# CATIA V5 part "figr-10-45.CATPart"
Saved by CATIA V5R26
Part number: Part1
Bounding box of the stored display mesh (mm): x -20 to 20, y -0.339 to 152.641, z -44.55 to 10.195
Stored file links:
  D:\_Deepak\CATIA\CATIA V5-6R2016_Deepak\Resources\Part files\Partfiles\c10_catia_v5_6r2016_prt\figr-10-45.CATPart
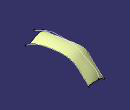
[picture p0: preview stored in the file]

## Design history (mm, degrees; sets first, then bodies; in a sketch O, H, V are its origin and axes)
Set1
  Plane1: type Offset, RefPlane yz-plane, Offset 20, reversed
  Sketch1 on yz-plane, origin (0, 0, 0), H (0, 1, 0), V (0, 0, 1)
    spline S1 through (-0.3393, -8.9363) (20.4957, 1.6782) (43.9804, 9.0119) (85.9797, 8.8277) (110.0875, 1.9736) (113.4186, 0.0053) (148.283, -20.6228) (152.6411, -30.7916)
  Sketch2 on Plane1, origin (-20, 0, 0), H (0, 1, 0), V (0, 0, 1)
    spline S1 through (0, -18.2863) (39.7074, -13.5111) (76.5446, -6.6894) (104.5136, -9.077) (112.3585, -15.8987) (129.7538, -32.6118) (143.3972, -44.5498)
  Plane2: type Offset, RefPlane yz-plane, Offset 20
  Sketch3 on Plane2, origin (20, 0, 0), H (0, 1, 0), V (0, 0, 1)
    spline S1 through (0, -29.0463) (25.3574, -14.3797) (67.652, -5.1704) (115.4039, -10.2866) (140.3031, -31.4339) (148.4891, -38.2556)
  Sweep1: type Conic, Guide ({sweepconicextendedguide Guide Sketch3, Reference Sketch1, Angle 15}; {sweepconicextendedguide Guide Sketch2, Reference Sketch1, Angle 15}), Parameter 0.5
Body1 (main body)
